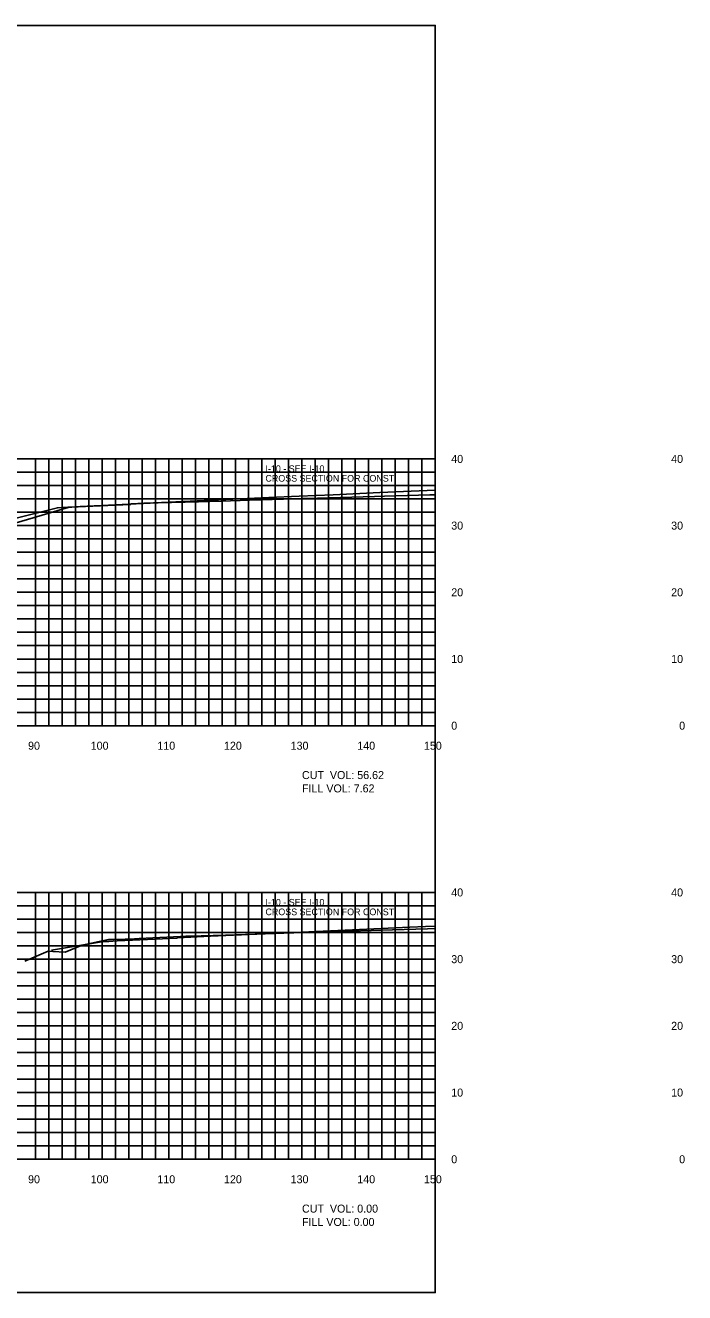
# Model space of a CAD drawing. Extents: x 1797652 to 1804159, y 242516 to 246906.
# Drawn here: x 1802393 to 1802491.9, y 242516 to 242706 of the extents above; entities that cross this region are included whole.
import ezdxf

# ---------------------------------------------------------------- set-up
doc = ezdxf.new("R2010")
doc.units = 0
for name, color, linetype in [('10', 7, 'Continuous'), ('3', 7, 'Continuous'), ('31', 7, 'Continuous'), ('60', 7, 'Continuous'), ('CL-CNST', 7, 'Continuous'), ('Level 62', 7, 'Continuous'), ('M-ROADS', 7, 'Continuous')]:
    doc.layers.add(name, color=color, linetype=linetype)

msp = doc.modelspace()

# ---------------------------------------------------------------- linework, layer by layer
msp.add_lwpolyline([(1802154.49, 242516), (1802454.49, 242516), (1802454.49, 242706), (1802154.49, 242706)], close=True)
at = {"layer": '60'}
for p, q in [((1802454.49, 242601), (1802454.49, 242641)), ((1802454.55, 242641), (1802454.49, 242641)), ((1802454.55, 242631), (1802454.49, 242631)), ((1802454.55, 242621), (1802454.49, 242621)), ((1802454.55, 242611), (1802454.49, 242611)), ((1802154.49, 242601), (1802454.49, 242601)), ((1802394.49, 242600.94), (1802394.49, 242601)), ((1802404.49, 242600.94), (1802404.49, 242601)), ((1802414.49, 242600.94), (1802414.49, 242601)), ((1802424.49, 242600.94), (1802424.49, 242601)), ((1802434.49, 242600.94), (1802434.49, 242601)), ((1802444.49, 242600.94), (1802444.49, 242601)), ((1802454.49, 242600.94), (1802454.49, 242601)), ((1802454.55, 242601), (1802454.49, 242601)), ((1802454.49, 242536), (1802454.49, 242576)), ((1802454.55, 242576), (1802454.49, 242576)), ((1802454.55, 242566), (1802454.49, 242566)), ((1802454.55, 242556), (1802454.49, 242556)), ((1802454.55, 242546), (1802454.49, 242546)), ((1802154.49, 242536), (1802454.49, 242536)), ((1802394.49, 242535.94), (1802394.49, 242536)), ((1802404.49, 242535.94), (1802404.49, 242536)), ((1802414.49, 242535.94), (1802414.49, 242536)), ((1802424.49, 242535.94), (1802424.49, 242536)), ((1802434.49, 242535.94), (1802434.49, 242536)), ((1802444.49, 242535.94), (1802444.49, 242536)), ((1802454.49, 242535.94), (1802454.49, 242536)), ((1802454.55, 242536), (1802454.49, 242536))]:
    msp.add_line(p, q, dxfattribs=at)
at = {"layer": 'CL-CNST'}
for points in [[(1802334.54, 242617.99), (1802357.55, 242623.69), (1802395.98, 242633.23), (1802397.78, 242633.68), (1802399.36, 242633.75), (1802399.8, 242633.77), (1802406.48, 242634.07), (1802408.79, 242634.18), (1802408.81, 242634.2), (1802408.87, 242634.25), (1802409.6, 242634.28), (1802409.88, 242634.29), (1802413.4, 242634.45), (1802421.97, 242634.84), (1802429.53, 242635.19), (1802434.07, 242635.39), (1802439.18, 242635.63), (1802446.16, 242635.94), (1802452.06, 242636.21), (1802454.49, 242636.32)], [(1802396.92, 242567.35), (1802402.01, 242568.19), (1802404.73, 242568.64), (1802405.53, 242568.67), (1802406.74, 242568.73), (1802412.44, 242568.99), (1802415.72, 242569.13), (1802415.77, 242569.19), (1802415.8, 242569.21), (1802416.46, 242569.24), (1802416.81, 242569.25), (1802420.75, 242569.43), (1802428.88, 242569.8), (1802432.21, 242569.95), (1802440.96, 242570.35), (1802450.69, 242570.79), (1802453.03, 242570.89), (1802454.49, 242570.96)]]:
    msp.add_lwpolyline(points, dxfattribs=at)
at = {"layer": 'Level 62'}
for p, q in [((1802154.49, 242641), (1802454.49, 242641)), ((1802394.49, 242601), (1802394.49, 242641)), ((1802396.49, 242601), (1802396.49, 242641)), ((1802398.49, 242601), (1802398.49, 242641)), ((1802400.49, 242601), (1802400.49, 242641)), ((1802402.49, 242601), (1802402.49, 242641)), ((1802404.49, 242601), (1802404.49, 242641)), ((1802406.49, 242601), (1802406.49, 242641)), ((1802408.49, 242601), (1802408.49, 242641)), ((1802410.49, 242601), (1802410.49, 242641)), ((1802412.49, 242601), (1802412.49, 242641)), ((1802414.49, 242601), (1802414.49, 242641)), ((1802416.49, 242601), (1802416.49, 242641)), ((1802418.49, 242601), (1802418.49, 242641)), ((1802420.49, 242601), (1802420.49, 242641)), ((1802422.49, 242601), (1802422.49, 242641)), ((1802424.49, 242601), (1802424.49, 242641)), ((1802426.49, 242601), (1802426.49, 242641)), ((1802428.49, 242601), (1802428.49, 242641)), ((1802430.49, 242601), (1802430.49, 242641)), ((1802432.49, 242601), (1802432.49, 242641)), ((1802434.49, 242601), (1802434.49, 242641)), ((1802436.49, 242601), (1802436.49, 242641)), ((1802438.49, 242601), (1802438.49, 242641)), ((1802440.49, 242601), (1802440.49, 242641)), ((1802442.49, 242601), (1802442.49, 242641)), ((1802444.49, 242601), (1802444.49, 242641)), ((1802446.49, 242601), (1802446.49, 242641)), ((1802448.49, 242601), (1802448.49, 242641)), ((1802450.49, 242601), (1802450.49, 242641)), ((1802452.49, 242601), (1802452.49, 242641)), ((1802454.49, 242601), (1802454.49, 242641)), ((1802154.49, 242639), (1802454.49, 242639)), ((1802154.49, 242637), (1802454.49, 242637)), ((1802154.49, 242635), (1802454.49, 242635)), ((1802154.49, 242633), (1802454.49, 242633)), ((1802154.49, 242631), (1802454.49, 242631)), ((1802154.49, 242629), (1802454.49, 242629)), ((1802154.49, 242627), (1802454.49, 242627)), ((1802154.49, 242625), (1802454.49, 242625)), ((1802154.49, 242623), (1802454.49, 242623)), ((1802154.49, 242621), (1802454.49, 242621)), ((1802154.49, 242619), (1802454.49, 242619)), ((1802154.49, 242617), (1802454.49, 242617)), ((1802154.49, 242615), (1802454.49, 242615)), ((1802154.49, 242613), (1802454.49, 242613)), ((1802154.49, 242611), (1802454.49, 242611)), ((1802154.49, 242609), (1802454.49, 242609)), ((1802154.49, 242607), (1802454.49, 242607)), ((1802154.49, 242605), (1802454.49, 242605)), ((1802154.49, 242603), (1802454.49, 242603)), ((1802154.49, 242601), (1802454.49, 242601)), ((1802154.49, 242576), (1802454.49, 242576)), ((1802394.49, 242536), (1802394.49, 242576)), ((1802396.49, 242536), (1802396.49, 242576)), ((1802398.49, 242536), (1802398.49, 242576)), ((1802400.49, 242536), (1802400.49, 242576)), ((1802402.49, 242536), (1802402.49, 242576)), ((1802404.49, 242536), (1802404.49, 242576)), ((1802406.49, 242536), (1802406.49, 242576)), ((1802408.49, 242536), (1802408.49, 242576)), ((1802410.49, 242536), (1802410.49, 242576)), ((1802412.49, 242536), (1802412.49, 242576)), ((1802414.49, 242536), (1802414.49, 242576)), ((1802416.49, 242536), (1802416.49, 242576)), ((1802418.49, 242536), (1802418.49, 242576)), ((1802420.49, 242536), (1802420.49, 242576)), ((1802422.49, 242536), (1802422.49, 242576)), ((1802424.49, 242536), (1802424.49, 242576)), ((1802426.49, 242536), (1802426.49, 242576)), ((1802428.49, 242536), (1802428.49, 242576)), ((1802430.49, 242536), (1802430.49, 242576)), ((1802432.49, 242536), (1802432.49, 242576)), ((1802434.49, 242536), (1802434.49, 242576)), ((1802436.49, 242536), (1802436.49, 242576)), ((1802438.49, 242536), (1802438.49, 242576)), ((1802440.49, 242536), (1802440.49, 242576)), ((1802442.49, 242536), (1802442.49, 242576)), ((1802444.49, 242536), (1802444.49, 242576)), ((1802446.49, 242536), (1802446.49, 242576)), ((1802448.49, 242536), (1802448.49, 242576)), ((1802450.49, 242536), (1802450.49, 242576)), ((1802452.49, 242536), (1802452.49, 242576)), ((1802454.49, 242536), (1802454.49, 242576)), ((1802154.49, 242574), (1802454.49, 242574)), ((1802154.49, 242572), (1802454.49, 242572)), ((1802154.49, 242570), (1802454.49, 242570)), ((1802154.49, 242568), (1802454.49, 242568)), ((1802154.49, 242566), (1802454.49, 242566)), ((1802154.49, 242564), (1802454.49, 242564)), ((1802154.49, 242562), (1802454.49, 242562)), ((1802154.49, 242560), (1802454.49, 242560)), ((1802154.49, 242558), (1802454.49, 242558)), ((1802154.49, 242556), (1802454.49, 242556)), ((1802154.49, 242554), (1802454.49, 242554)), ((1802154.49, 242552), (1802454.49, 242552)), ((1802154.49, 242550), (1802454.49, 242550)), ((1802154.49, 242548), (1802454.49, 242548)), ((1802154.49, 242546), (1802454.49, 242546)), ((1802154.49, 242544), (1802454.49, 242544)), ((1802154.49, 242542), (1802454.49, 242542)), ((1802154.49, 242540), (1802454.49, 242540)), ((1802154.49, 242538), (1802454.49, 242538)), ((1802154.49, 242536), (1802454.49, 242536))]:
    msp.add_line(p, q, dxfattribs=at)
at = {"layer": 'M-ROADS'}
for points in [[(1802389.42, 242630.78), (1802399.41, 242633.71), (1802400.57, 242633.81), (1802401.19, 242633.86), (1802406.51, 242634.11), (1802409.53, 242634.24), (1802410.65, 242634.33), (1802410.79, 242634.34), (1802411.72, 242634.37), (1802412.9, 242634.4), (1802418.96, 242634.57), (1802422.36, 242634.67), (1802426.61, 242634.81), (1802433.41, 242635.02), (1802434.45, 242635.05), (1802435.1, 242635.07), (1802445.37, 242635.37), (1802446.89, 242635.41), (1802453.7, 242635.61), (1802454.49, 242635.63)], [(1802392.9, 242565.7), (1802396.4, 242567.19), (1802397.1, 242567.15), (1802398.96, 242567.04), (1802401.5, 242568.1), (1802405.47, 242568.95), (1802406.23, 242568.96), (1802407.94, 242568.99), (1802408.6, 242569.02), (1802410.07, 242569.09), (1802416.28, 242569.39), (1802417.05, 242569.43), (1802417.53, 242569.46), (1802423.03, 242569.62), (1802428.97, 242569.81), (1802431.75, 242569.91), (1802436.24, 242570.05), (1802439.58, 242570.15), (1802441.65, 242570.22), (1802448.06, 242570.42), (1802453.35, 242570.57), (1802454.49, 242570.6)]]:
    msp.add_lwpolyline(points, dxfattribs=at)

# ---------------------------------------------------------------- texts
at = {"layer": '10'}
for s, p in [('90', (1802393.39, 242597.4)), ('100', (1802402.79, 242597.4)), ('110', (1802412.79, 242597.4)), ('120', (1802422.79, 242597.4)), ('130', (1802432.79, 242597.4)), ('140', (1802442.79, 242597.4)), ('150', (1802452.79, 242597.4)), ('CUT  VOL: 56.62', (1802434.49, 242593)), ('FILL VOL: 7.62', (1802434.49, 242591)), ('90', (1802393.39, 242532.4)), ('100', (1802402.79, 242532.4)), ('110', (1802412.79, 242532.4)), ('120', (1802422.79, 242532.4)), ('130', (1802432.79, 242532.4)), ('140', (1802442.79, 242532.4)), ('150', (1802452.79, 242532.4)), ('CUT  VOL: 0.00', (1802434.49, 242528)), ('FILL VOL: 0.00', (1802434.49, 242526))]:
    msp.add_text(s, height=1.2, dxfattribs=at).set_placement(p)
at = {"layer": '3'}
for s, p in [('I-10 - SEE I-10', (1802429.01, 242639.03)), ('CROSS SECTION FOR CONST ', (1802429.01, 242637.59)), ('I-10 - SEE I-10', (1802429.01, 242574.03)), ('CROSS SECTION FOR CONST ', (1802429.01, 242572.59))]:
    msp.add_text(s, height=1, dxfattribs=at).set_placement(p)
at = {"layer": '31'}
for s, p in [('40', (1802456.89, 242640.4)), ('40', (1802489.89, 242640.4)), ('30', (1802456.89, 242630.4)), ('30', (1802489.89, 242630.4)), ('20', (1802456.89, 242620.4)), ('20', (1802489.89, 242620.4)), ('10', (1802456.89, 242610.4)), ('10', (1802489.89, 242610.4)), ('0', (1802456.89, 242600.4)), ('0', (1802491.09, 242600.4)), ('40', (1802456.89, 242575.4)), ('40', (1802489.89, 242575.4)), ('30', (1802456.89, 242565.4)), ('30', (1802489.89, 242565.4)), ('20', (1802456.89, 242555.4)), ('20', (1802489.89, 242555.4)), ('10', (1802456.89, 242545.4)), ('10', (1802489.89, 242545.4)), ('0', (1802456.89, 242535.4)), ('0', (1802491.09, 242535.4))]:
    msp.add_text(s, height=1.2, dxfattribs=at).set_placement(p)

doc.saveas('drawing.dxf')
